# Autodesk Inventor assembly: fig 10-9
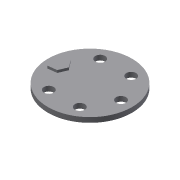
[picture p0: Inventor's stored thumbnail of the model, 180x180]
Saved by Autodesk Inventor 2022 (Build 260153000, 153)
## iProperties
Created: 2008-05
Part Number: fig 10-9
Document SubType Name: Assembly
Designer: CADCIM
Author: CADCIM
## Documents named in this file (3)
- D:\PROJECTS_2021\Resources\Part Files\c10_Inv_2021_prt\fig 10-9.iam
- D:\PROJECTS_2021\Resources\Part Files\c10_Inv_2021_prt\Part4.ipt
- D:\PROJECTS_2021\Resources\Part Files\c10_Inv_2021_prt\Part5.ipt
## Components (2 placed, 2 different names)
1. Part4:1
2. Part5:1
